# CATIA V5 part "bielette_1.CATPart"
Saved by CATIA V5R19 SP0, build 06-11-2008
Part number: Pièce1
Publications: "axe_pivot_biellette1_levier", "axe_pivot_biellette1_biellette2_biellette3", "Plan.1"
Bounding box of the stored display mesh (mm): x 0 to 0, y 410 to 580, z -20 to 20
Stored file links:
  C:\Users\Thibaud\Desktop\IFMA\thinkmotion\IAO\modele_catia\squelette\bielette_1.CATPart
  C:\Users\Thibaud\Desktop\IFMA\thinkmotion\IAO\modele_catia\squelette\ass_chariot.CATProduct
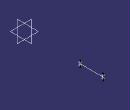
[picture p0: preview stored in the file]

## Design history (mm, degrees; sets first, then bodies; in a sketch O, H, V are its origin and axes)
Set1
  Point1 "Point.3": linked copy from another document
  Point2: linked copy from another document
  Plane1: linked copy from another document
Body1 (main body)
  Line1: type PtPt, SecondPoint Point2, FirstPoint Point1
  Line2 "axe_pivot_biellette1_levier": type PtDir, Direction Plane1, Start -20, End 20, RefPoint Point1
  Line3 "axe_pivot_biellette1_biellette2_biellette3": type PtDir, Direction Plane1, Start -20, End 20, RefPoint Point2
